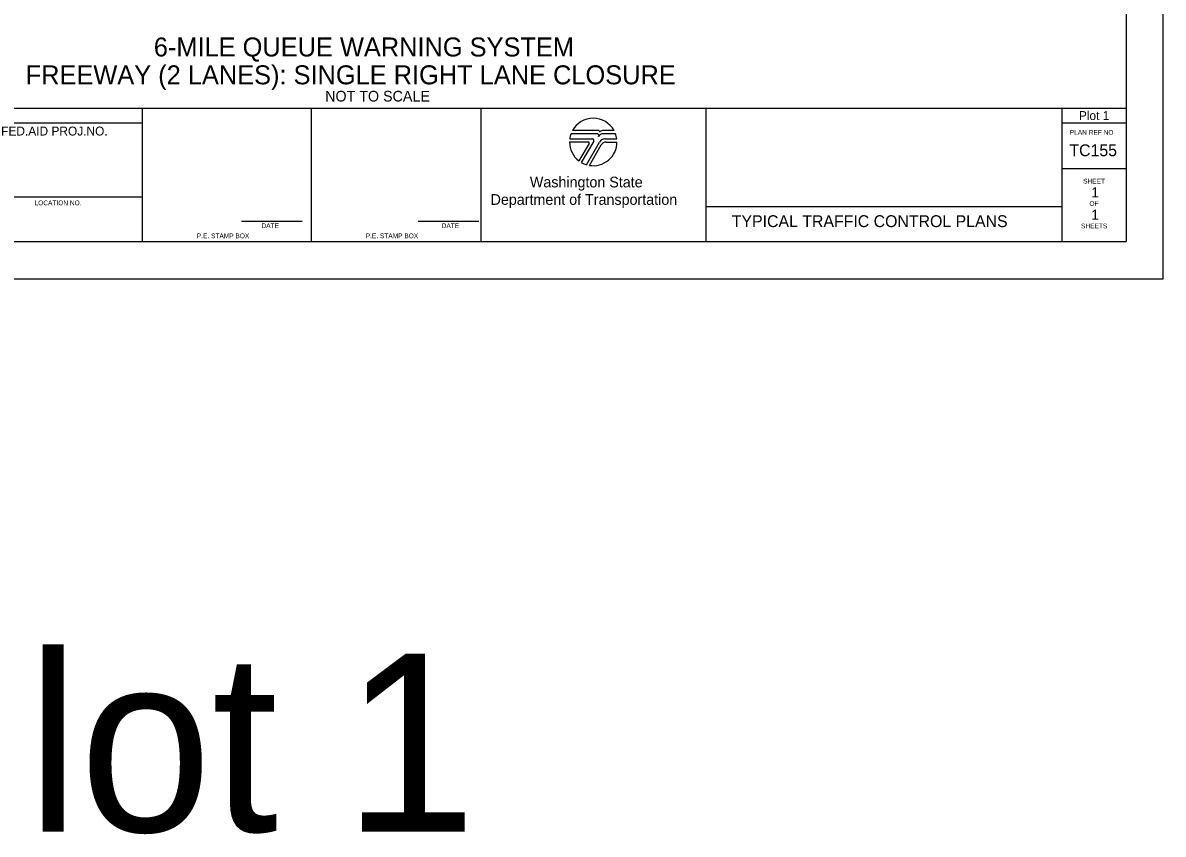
# Model space of a CAD drawing. Extents: x 99999.1 to 100035.7, y 99995 to 100010.7.
# Drawn here: x 100006.45 to 100016.06, y 99995.01 to 100001.84 of the extents above; entities that cross this region are included whole.
import ezdxf

# ---------------------------------------------------------------- set-up
doc = ezdxf.new("R2010")
doc.units = 0
for name, color, linetype in [('SH_DE_DetailHeading1Text', 7, 'Continuous'), ('SH_DE_DetailHeading3Text', 7, 'Continuous'), ('SH_GI_PlotLimits', 7, 'Continuous'), ('SH_GI_SheetBorder', 7, 'Continuous'), ('SH_GI_SheetLocationText', 7, 'Continuous'), ('SH_GI_SheetTextInCells', 7, 'Continuous'), ('SH_GI_TitleBlockText', 7, 'Continuous'), ('SH_GI_WSDOTLogo', 7, 'Continuous')]:
    doc.layers.add(name, color=color, linetype=linetype)

msp = doc.modelspace()

# ---------------------------------------------------------------- linework, layer by layer
at = {"layer": 'SH_GI_PlotLimits'}
msp.add_lwpolyline([(99999.0625, 99999.6875), (100016.0625, 99999.6875), (100016.0625, 100010.6875), (99999.0625, 100010.6875)], close=True, dxfattribs=at)
at = {"layer": 'SH_GI_SheetBorder'}
for p, q in [((100015.75, 100010.375), (100015.75, 100000)), ((100000, 100001.1259), (100015.75, 100001.1259)), ((100007.4566, 100000), (100007.4566, 100001.1259)), ((100008.8828, 100000), (100008.8828, 100001.1259)), ((100010.3089, 100001.1259), (100010.3089, 100000)), ((100012.2055, 100001.1259), (100012.2055, 100000)), ((100015.2079, 100001.1259), (100015.2079, 100000)), ((100000, 100001.0008), (100007.4566, 100001.0008)), ((100015.2079, 100001.0008), (100015.75, 100001.0008)), ((100015.2079, 100000.6176), (100015.75, 100000.6176)), ((100007.4566, 100000.3753), (100005.4466, 100000.3753)), ((100012.2055, 100000.2955), (100015.2079, 100000.2955)), ((100008.2903, 100000.1733), (100008.802, 100000.1733)), ((100009.7797, 100000.1733), (100010.2914, 100000.1733)), ((100000, 100000), (100015.75, 100000))]:
    msp.add_line(p, q, dxfattribs=at)
at = {"layer": 'SH_GI_WSDOTLogo'}
for p, q in [((100011.2894, 100000.9094), (100011.0697, 100000.9094)), ((100011.303, 100000.9354), (100011.0815, 100000.9354)), ((100011.433, 100000.9354), (100011.3351, 100000.9354)), ((100011.343, 100000.9094), (100011.3429, 100000.9094)), ((100011.4448, 100000.9094), (100011.343, 100000.9094)), ((100011.0572, 100000.84), (100011.2148, 100000.84)), ((100011.059, 100000.8661), (100011.2496, 100000.8661)), ((100011.222, 100000.8277), (100011.1364, 100000.6807)), ((100011.261, 100000.8464), (100011.1567, 100000.6672)), ((100011.1989, 100000.6487), (100011.3089, 100000.839)), ((100011.2244, 100000.6428), (100011.3242, 100000.8156)), ((100011.3558, 100000.8661), (100011.4555, 100000.8661)), ((100011.3655, 100000.8394), (100011.4572, 100000.8394))]:
    msp.add_line(p, q, dxfattribs=at)
for centre, radius, start, end in [((100011.2572, 100000.84), 0.2, 28.47865, 151.53204), ((100011.2572, 100000.84), 0.2, 159.69598, 172.50569), ((100011.2894, 100000.8946), 0.0148, 327.8418, 89.99855), ((100011.3429, 100000.861), 0.0484, 89.99529, 147.82376), ((100011.303, 100000.9263), 0.00903, 329.87418, 90.00328), ((100011.3352, 100000.9066), 0.0287, 90.00721, 148.16763), ((100011.2572, 100000.84), 0.2, 7.49431, 20.29406), ((100011.2572, 100000.84), 0.2, 179.99864, 232.84327), ((100011.2149, 100000.8318), 0.0082, 329.74356, 90), ((100011.2572, 100000.84), 0.2, 260.54554, 359.80857), ((100011.2497, 100000.853), 0.0131, 329.76834, 90), ((100011.3558, 100000.8119), 0.0542, 90, 149.99738), ((100011.3654, 100000.7918), 0.0476, 90, 150.05432), ((100011.2572, 100000.84), 0.2, 239.79292, 253.0448)]:
    msp.add_arc(centre, radius, start, end, dxfattribs=at)

# ---------------------------------------------------------------- texts
at = {"layer": 'SH_DE_DetailHeading1Text'}
for s, p in [('6-MILE QUEUE WARNING SYSTEM', (100007.5522, 100001.5606)), ('FREEWAY (2 LANES): SINGLE RIGHT LANE CLOSURE', (100006.4718, 100001.3259))]:
    msp.add_text(s, height=0.16, rotation=360, dxfattribs=at).set_placement(p)
at = {"layer": 'SH_DE_DetailHeading3Text'}
msp.add_text('NOT TO SCALE', height=0.09, dxfattribs=at).set_placement((100008.9969, 100001.1809))
at = {"layer": 'SH_GI_SheetBorder'}
msp.add_text('PLAN REF NO', height=0.040032, dxfattribs=at).set_placement((100015.2747, 100000.9008))
at = {"layer": 'SH_GI_SheetLocationText'}
for height, p in [(0.075, (100015.3518, 100001.025)), (1.5, (100005.1422, 99995.0267))]:
    msp.add_text('Plot 1', height=height, dxfattribs=at).set_placement(p)
at = {"layer": 'SH_GI_SheetTextInCells'}
for s, height, p in [('FED.AID PROJ.NO.', 0.07506, (100006.2652, 100000.8945)), ('Washington State', 0.090072, (100010.7229, 100000.4571)), ('SHEET', 0.04003, (100015.3877, 100000.4896)), ('Department of Transportation', 0.090072, (100010.3916, 100000.3101)), ('LOCATION NO.', 0.040032, (100006.5465, 100000.3067)), ('OF', 0.04003, (100015.4406, 100000.3008)), ('DATE', 0.04003, (100008.4597, 100000.1141)), ('DATE', 0.04003, (100009.9794, 100000.1141)), ('SHEETS', 0.04003, (100015.3698, 100000.112)), ('P.E. STAMP BOX', 0.040032, (100007.915, 100000.0286)), ('P.E. STAMP BOX', 0.040032, (100009.339, 100000.0286))]:
    msp.add_text(s, height=height, dxfattribs=at).set_placement(p)
at = {"layer": 'SH_GI_TitleBlockText'}
for s, height, p in [('TC155', 0.1, (100015.2718, 100000.72)), ('1', 0.085, (100015.4566, 100000.3723)), ('TYPICAL TRAFFIC CONTROL PLANS', 0.1, (100012.4251, 100000.1224)), ('1', 0.085, (100015.4566, 100000.1843))]:
    msp.add_text(s, height=height, dxfattribs=at).set_placement(p)

doc.saveas('drawing.dxf')
